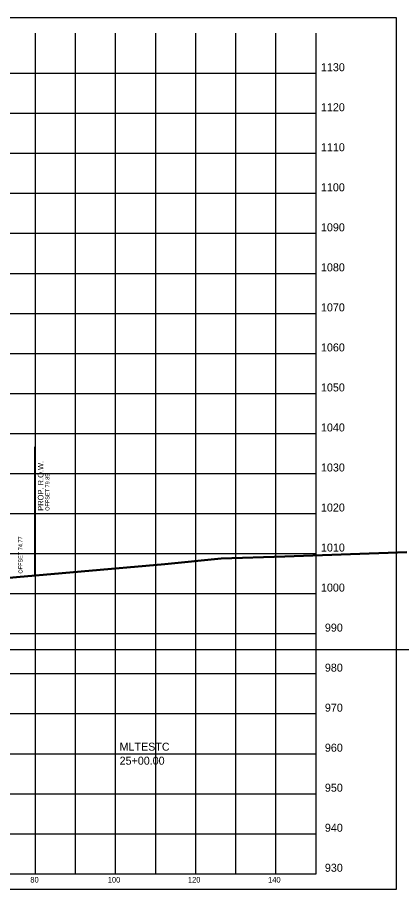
# Model space of a CAD drawing. Extents: x 1131015 to 1136271, y 133453 to 174329.
# Drawn here: x 1132416 to 1132511.8, y 156607.7 to 156825.6 of the extents above; entities that cross this region are included whole.
import ezdxf

# ---------------------------------------------------------------- set-up
doc = ezdxf.new("R2010")
doc.units = 0
for name, color, linetype in [('DESIGN - ROW - Right-of-Way and Easement Labels', 7, 'Continuous'), ('DESIGN - ROW - Right-of-Way Linework', 7, 'Continuous'), ('DESIGN - SHEET - Corner Text', 7, 'Continuous'), ('DESIGN - SHEET - Light Grid', 7, 'Continuous'), ('DESIGN - SHEET - Linework', 7, 'Continuous'), ('DESIGN - SHEET - Plot Shape', 7, 'Continuous'), ('DESIGN - TYPICAL - Slope Tie Text', 7, 'Continuous'), ('DESIGN - TYPICAL - Warning Text', 7, 'Continuous'), ('SURVEY - GROUND - Bottom of Topsoil Layer', 7, 'Continuous'), ('SURVEY - GROUND - Top of Ground', 7, 'Continuous')]:
    doc.layers.add(name, color=color, linetype=linetype)

msp = doc.modelspace()

# ---------------------------------------------------------------- linework, layer by layer
at = {"layer": 'DESIGN - ROW - Right-of-Way Linework'}
msp.add_line((1132420.31, 156686.34), (1132420.31, 156718.34), dxfattribs=at)
at = {"layer": 'DESIGN - SHEET - Light Grid'}
msp.add_line((1132340.46, 156667.66), (1132640.46, 156667.66), dxfattribs=at)
at = {"layer": 'DESIGN - SHEET - Linework'}
for p, q in [((1132420.46, 156611.66), (1132420.46, 156821.66)), ((1132430.46, 156611.66), (1132430.46, 156821.66)), ((1132440.46, 156611.66), (1132440.46, 156821.66)), ((1132450.46, 156611.66), (1132450.46, 156821.66)), ((1132460.46, 156611.66), (1132460.46, 156821.66)), ((1132470.46, 156611.66), (1132470.46, 156821.66)), ((1132480.46, 156611.66), (1132480.46, 156821.66)), ((1132190.46, 156811.66), (1132490.46, 156811.66)), ((1132190.46, 156801.66), (1132490.46, 156801.66)), ((1132190.46, 156791.66), (1132490.46, 156791.66)), ((1132190.46, 156781.66), (1132490.46, 156781.66)), ((1132190.46, 156771.66), (1132490.46, 156771.66)), ((1132190.46, 156761.66), (1132490.46, 156761.66)), ((1132190.46, 156751.66), (1132490.46, 156751.66)), ((1132190.46, 156741.66), (1132490.46, 156741.66)), ((1132190.46, 156731.66), (1132490.46, 156731.66)), ((1132190.46, 156721.66), (1132490.46, 156721.66)), ((1132190.46, 156711.66), (1132490.46, 156711.66)), ((1132190.46, 156701.66), (1132490.46, 156701.66)), ((1132190.46, 156691.66), (1132490.46, 156691.66)), ((1132190.46, 156681.66), (1132490.46, 156681.66)), ((1132190.46, 156671.66), (1132490.46, 156671.66)), ((1132190.46, 156661.66), (1132490.46, 156661.66)), ((1132190.46, 156651.66), (1132490.46, 156651.66)), ((1132190.46, 156641.66), (1132490.46, 156641.66)), ((1132190.46, 156631.66), (1132490.46, 156631.66)), ((1132190.46, 156621.66), (1132490.46, 156621.66))]:
    msp.add_line(p, q, dxfattribs=at)
msp.add_lwpolyline([(1132190.46, 156821.66), (1132190.46, 156611.66), (1132490.46, 156611.66), (1132490.46, 156821.66)], dxfattribs=at)
at = {"layer": 'DESIGN - SHEET - Plot Shape'}
msp.add_lwpolyline([(1132170.46, 156825.6), (1132510.46, 156825.6), (1132510.46, 156607.72), (1132170.46, 156607.72)], close=True, dxfattribs=at)
at = {"layer": 'SURVEY - GROUND - Bottom of Topsoil Layer'}
for p, q in [((1132466.76, 156690.35), (1132482.68, 156690.8)), ((1132482.68, 156690.8), (1132513.15, 156691.89)), ((1132410.11, 156685.21), (1132452.78, 156688.9)), ((1132452.78, 156688.9), (1132466.76, 156690.35))]:
    msp.add_line(p, q, dxfattribs=at)
at = {"layer": 'SURVEY - GROUND - Top of Ground'}
for p, q in [((1132452.78, 156689.15), (1132466.76, 156690.6)), ((1132466.76, 156690.6), (1132482.68, 156691.05)), ((1132482.68, 156691.05), (1132513.15, 156692.14)), ((1132410.11, 156685.46), (1132452.78, 156689.15))]:
    msp.add_line(p, q, dxfattribs=at)

# ---------------------------------------------------------------- texts
at = {"layer": 'DESIGN - ROW - Right-of-Way and Easement Labels'}
for s, height, p in [('PROP. R.O.W.', 1.4, (1132422.46, 156702.34)), ('OFFSET 79.85', 1, (1132423.96, 156702.34))]:
    msp.add_text(s, height=height, rotation=90, dxfattribs=at).set_placement(p)
at = {"layer": 'DESIGN - SHEET - Corner Text'}
for s, height, p in [('1130', 2, (1132491.7, 156812.16)), ('1120', 2, (1132491.7, 156802.16)), ('1110', 2, (1132491.7, 156792.16)), ('1100', 2, (1132491.7, 156782.16)), ('1090', 2, (1132491.7, 156772.16)), ('1080', 2, (1132491.7, 156762.16)), ('1070', 2, (1132491.7, 156752.16)), ('1060', 2, (1132491.7, 156742.16)), ('1050', 2, (1132491.7, 156732.16)), ('1040', 2, (1132491.7, 156722.16)), ('1030', 2, (1132491.7, 156712.16)), ('1020', 2, (1132491.7, 156702.16)), ('1010', 2, (1132491.7, 156692.16)), ('1000', 2, (1132491.7, 156682.16)), ('990', 2, (1132492.68, 156672.16)), ('980', 2, (1132492.68, 156662.16)), ('970', 2, (1132492.68, 156652.16)), ('960', 2, (1132492.68, 156642.16)), ('950', 2, (1132492.68, 156632.16)), ('940', 2, (1132492.68, 156622.16)), ('930', 2, (1132492.68, 156612.16)), ('80', 1.4, (1132419.19, 156609.46)), ('100', 1.4, (1132438.51, 156609.46)), ('120', 1.4, (1132458.51, 156609.46)), ('140', 1.4, (1132478.51, 156609.46))]:
    msp.add_text(s, height=height, dxfattribs=at).set_placement(p)
at = {"layer": 'DESIGN - TYPICAL - Slope Tie Text'}
msp.add_text('OFFSET 74.77', height=1, rotation=90, dxfattribs=at).set_placement((1132417.23, 156686.65))
at = {"layer": 'DESIGN - TYPICAL - Warning Text'}
for s, p in [('MLTESTC', (1132441.46, 156642.41)), ('25+00.00', (1132441.46, 156638.91))]:
    msp.add_text(s, height=2, dxfattribs=at).set_placement(p)

doc.saveas('drawing.dxf')
